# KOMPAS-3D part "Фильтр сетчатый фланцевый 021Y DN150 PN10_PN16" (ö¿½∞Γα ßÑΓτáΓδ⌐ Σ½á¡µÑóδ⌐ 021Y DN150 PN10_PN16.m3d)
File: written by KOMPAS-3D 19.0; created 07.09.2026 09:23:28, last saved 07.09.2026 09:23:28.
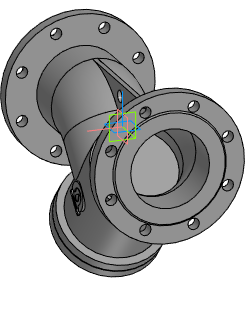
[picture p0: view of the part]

Document properties: Автор: Энергия; Полное имя файла: Z:\3.Личные\sachek\Dendor\_3D для проектировщиков\8.3 Фильтр сетчатый 021Y\021Y_STP\Фильтр сетчатый фланцевый 021Y DN150 PN10_PN16.m3d

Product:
- Part/product: Фильтр сетчатый фланцевый 021Y DN150 PN10_PN16

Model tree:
1. Операция без истории:1  (labels: Фильтр сетчатый фланцевый 021Y DN150 PN10_PN16)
